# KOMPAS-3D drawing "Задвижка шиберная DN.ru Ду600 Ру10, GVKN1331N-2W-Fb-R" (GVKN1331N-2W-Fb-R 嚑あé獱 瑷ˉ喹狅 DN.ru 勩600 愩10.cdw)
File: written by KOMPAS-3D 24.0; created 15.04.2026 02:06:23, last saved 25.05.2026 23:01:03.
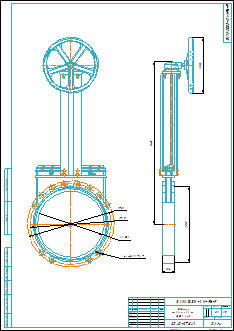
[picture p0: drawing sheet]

Document properties: Автор: DN.ru; Форматы листов документа: A2; Полное имя файла: GVKN1331N-2W-Fb-R Задвижка шиберная DN.ru Ду600 Ру10.m3d; Масса: 281; Наименование: Задвижка шиберная DN.ru Ду600 Ру10; Количество листов документа: 1; Примечание: D040-07841

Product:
- Part/product: Задвижка шиберная DN.ru Ду600 Ру10  | designation GVKN1331N-2W-Fb-R
    Масса: 281
    Раздел спецификации: Прочие изделия
    Примечание: D040-07841

Views: Вид 1, Вид:1, Проекционный вид 2
Referenced files in C:\Работа\GVKN1331N-2W-Fb-R Задвижка шиберная DN.ru Ду400-600 Ру10\DN400\: GVKN1331N-2W-Fb-R Задвижка шиберная DN.ru Ду400 Ру10.m3d
Referenced files in C:\Работа\GVKN1331N-2W-Fb-R Задвижка шиберная DN.ru Ду400-600 Ру10\DN600\: GVKN1331N-2W-Fb-R Задвижка шиберная DN.ru Ду600 Ру10.m3d
Referenced files in C:\Program Files\ASCON\KOMPAS-3D v24\Templates\: Чертеж_DN.ru.cdt
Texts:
  DN600
  GVKN1331N-2W-Fb-R
  Чертеж_DN.ru.cdt
  Задвижка
  шиберная DN.ru
  Ду600 Ру10
  Задвижка шиберная DN.ru Ду600 Ру10
  GVKN1331N-2W-Fb-R Задвижка шиберная DN.ru Ду600 Ру10
Dimensions and other numbers on the sheet: 0; 3; 2; 4; 780; 725; 24 отв.; 27; 1; 1460; 682; 114; 500; 1:5; 281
